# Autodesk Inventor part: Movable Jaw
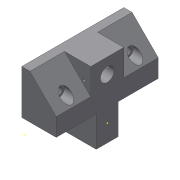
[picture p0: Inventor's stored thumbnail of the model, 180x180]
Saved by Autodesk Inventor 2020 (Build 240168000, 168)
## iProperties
Created: 2002-02
Part Number: Movable Jaw
Document SubType Name: Modeling
Designer: ***
Density: 1 g/cm^3
Material: Generic
Mass: 56.5588 g
Surface Area: 124.299 cm^2
Volume: 56.5588 cm^3
Appearance: Default
Control State: 0
Master: False
Checked Out: False
Shininess: 77.0
Length Units: 11269
Angle Units: 11279
Time Units: 11290
Mass Units: 11283
Length Display Precision: 3
Angle Display Precision: 2
Density: 0.0
Volumn: 0.0
Area: 0.0
PropertySet Name: Model Information
Author: ***
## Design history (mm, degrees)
sketch "Sketch2"
  geometry: L1 (2.39, 41.509)-(2.39, 9.509); L2 (2.39, 9.509)-(-22.61, 9.509); L3 (-22.61, 9.509)-(-22.61, 22.509); L4 (-22.61, 22.509)-(-3.61, 41.509); L5 (-3.61, 41.509)-(2.39, 41.509)
  constraints: 10 end point, 2 parallel, 1 perpendicular, 1 vertical
  dimensions: "d0" = 25 distance of L1.end L2.end; "d2" = 13 distance of L2.end L3.end; "d3" = 32 distance between parallel lines of L5 L2; "d4" = 6 distance of L4.end L1.start
extrude "Extrusion1" new body sketch "Sketch2" stored distance "d5" = 74; taper "d6" = 0 deg
sketch "Sketch3"
  geometry: L1 (-19, 25)-(11, 25); L2 (11, 25)-(11, 49); L3 (11, 49)-(-19, 49); L4 (-19, 49)-(-19, 25); L5 (0, 0)-(13, 0) reference; L6 (-19, 74)-(-19, 0) reference; L7 (11.924, 29)-(35, 29); L8 (35, 29)-(35, 45); L9 (35, 45)-(11.924, 45); L10 (11.924, 45)-(11.924, 29); L11 (13, 74)-(13, 0) reference
  constraints: 16 end point, 4 parallel, 2 horizontal, 2 perpendicular, 1 collinear
  dimensions: "d7" = 24 distance of L3.end L1.start; "d8" = 30 distance of L1.start L1.end; "d9" = 25 distance between parallel lines of L5 L1; "d10" = 16 distance of L7.end L8.end; "d11" = 4 distance between parallel lines of L3 L9; "d12" = 22 distance between parallel lines of L11 L8
extrude "Extrusion2" join sketch "Sketch3" distance "d13" = 25; taper "d14" = 0 deg
sketch "Sketch4"
  geometry: L1 (-19, -25)-(-19, -49) reference; L2 (-19, -49)-(0, -49) reference; 1 further point
  dimensions: "d15" = 11 distance from line of L1 point (-8, -37); "d16" = 12 distance from line of L2 point (-8, -37)
hole "Hole1" sketch "Sketch4" at (-8, -37) diameter "d17" = 10; stored, may be unused: countersink angle "d21" = 82 deg, drill point angle "d23" = 0 deg; dims "d18" = 6, "d19" = 4, "d20" = 2, "d22" = 13
sketch "Sketch5"
  geometry: L1 (-19, -49)-(-19, -74) reference; L2 (0, -74)-(13, -74) reference; 1 further point
  dimensions: "d24" = 14 distance from line of L1 point (-5, -62); "d25" = 12 distance from line of L2 point (-5, -62)
hole "Hole2" sketch "Sketch5" at (-5, -62) diameter "d26" = 4.917; stored, may be unused: countersink angle "d30" = 82 deg, drill point angle "d32" = 0 deg; dims "d27" = 12, "d28" = 8, "d29" = 10, "d31" = 17.1
mirror "Mirror1"
sketch "Sketch6"
  geometry: L1 (0, 19)-(0, 0) reference; 1 further point
  dimensions: "d33" = 5 distance from line of L1 point (-5, 8); "d34" = 11 vertical distance of L1.start point (-5, 8)
hole "Hole3" sketch "Sketch6" at (-5, 8) diameter "d35" = 2; stored, may be unused: countersink angle "d39" = 82 deg, drill point angle "d41" = 0 deg; dims "d36" = 6, "d37" = 8, "d38" = 10, "d40" = 13
sketch "Sketch7"
  geometry: 1 further point
sketch "Sketch8"
  geometry: 1 further point
body "Solid1"
